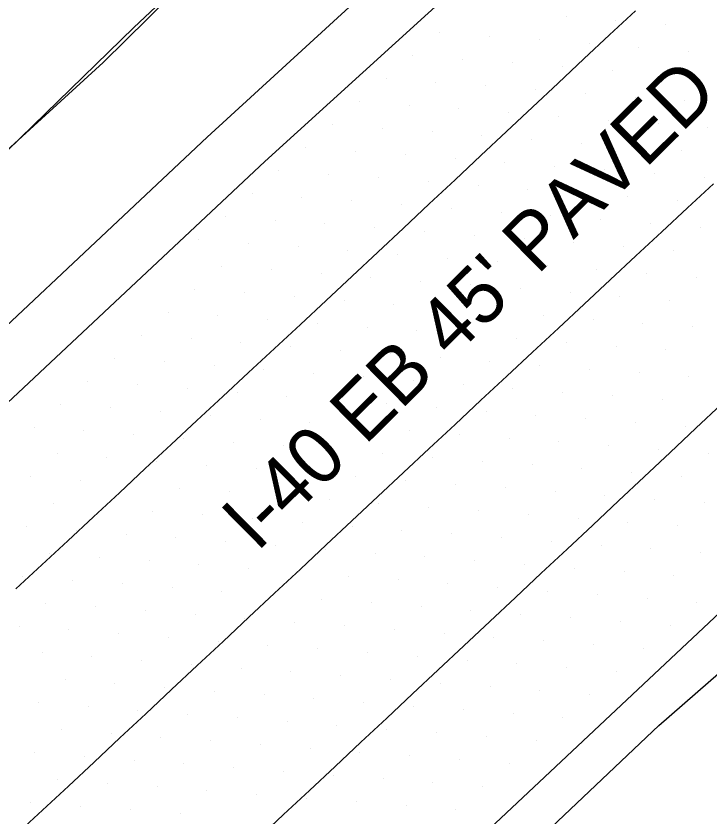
# Model space of a CAD drawing. Extents: x 1548934 to 1561348, y 809680 to 824075.
# Drawn here: x 1552081 to 1552130.1, y 810906.3 to 810963 of the extents above; entities that cross this region are included whole.
import ezdxf

# ---------------------------------------------------------------- set-up
doc = ezdxf.new("R2010")
doc.units = 0
for name, color, linetype in [('E_NCDOT_Vertical_Profile_Ground_Line', 7, 'Continuous'), ('Exist DTM Scan Elevation Point', 7, 'Continuous'), ('Exist Guardrail Cable Guide Rail', 7, 'Continuous'), ('Exist Roads EOP Text', 7, 'Continuous'), ('P_RDY_Terminator_Cell', 7, 'Continuous'), ('PH Exist DTM Breakline', 7, 'Continuous')]:
    doc.layers.add(name, color=color, linetype=linetype)

msp = doc.modelspace()

# ---------------------------------------------------------------- linework, layer by layer
at = {"layer": 'E_NCDOT_Vertical_Profile_Ground_Line'}
for points in [[(1551914.733, 810783.326), (1551936.975, 810803.465), (1551959.182, 810823.64), (1551981.364, 810843.843), (1552003.226, 810864.385), (1552025.148, 810884.865), (1552043.694, 810901.636), (1552062.107, 810918.548), (1552080.398, 810935.59), (1552098.623, 810952.701), (1552117.113, 810969.532), (1552135.352, 810986.629), (1552153.57, 811003.748), (1552171.877, 811020.773), (1552190.026, 811037.966), (1552208.08, 811055.241), (1552226.135, 811072.468)], [(1551911.033, 810719.298), (1551923.424, 810730.276), (1551945.867, 810750.201), (1551968.023, 810770.431), (1551990.144, 810790.698), (1552012.283, 810810.947), (1552034.431, 810831.185), (1552056.423, 810851.59), (1552074.962, 810868.368), (1552093.191, 810885.476), (1552111.451, 810902.55), (1552129.675, 810919.663), (1552147.898, 810936.778), (1552166.164, 810953.847), (1552184.38, 810970.968), (1552202.566, 810988.121), (1552220.715, 811005.314), (1552238.802, 811022.599), (1552256.952, 811039.884)]]:
    msp.add_lwpolyline(points, dxfattribs=at)
at = {"layer": 'Exist DTM Scan Elevation Point'}
for p, q in [((1552119.942, 810962.937), (1552119.942, 810962.937)), ((1552123.467, 810962.669), (1552123.467, 810962.669)), ((1552126.992, 810962.401), (1552126.992, 810962.401)), ((1552110.995, 810961.843), (1552110.995, 810961.843)), ((1552114.521, 810961.576), (1552114.521, 810961.576)), ((1552118.046, 810961.308), (1552118.046, 810961.308)), ((1552121.571, 810961.04), (1552121.571, 810961.04)), ((1552125.096, 810960.773), (1552125.096, 810960.773)), ((1552128.621, 810960.505), (1552128.621, 810960.505)), ((1552109.099, 810960.214), (1552109.099, 810960.214)), ((1552112.624, 810959.947), (1552112.624, 810959.947)), ((1552116.149, 810959.679), (1552116.149, 810959.679)), ((1552119.675, 810959.411), (1552119.675, 810959.411)), ((1552123.2, 810959.144), (1552123.2, 810959.144)), ((1552126.725, 810958.876), (1552126.725, 810958.876)), ((1552107.203, 810958.585), (1552107.203, 810958.585)), ((1552110.728, 810958.318), (1552110.728, 810958.318)), ((1552114.253, 810958.05), (1552114.253, 810958.05)), ((1552117.778, 810957.782), (1552117.778, 810957.782)), ((1552121.303, 810957.515), (1552121.303, 810957.515)), ((1552105.306, 810956.956), (1552105.306, 810956.956)), ((1552124.828, 810957.247), (1552124.828, 810957.247)), ((1552128.354, 810956.979), (1552128.354, 810956.979)), ((1552108.831, 810956.689), (1552108.831, 810956.689)), ((1552112.356, 810956.421), (1552112.356, 810956.421)), ((1552115.882, 810956.154), (1552115.882, 810956.154)), ((1552119.407, 810955.886), (1552119.407, 810955.886)), ((1552103.41, 810955.327), (1552103.41, 810955.327)), ((1552122.932, 810955.618), (1552122.932, 810955.618)), ((1552126.457, 810955.351), (1552126.457, 810955.351)), ((1552106.935, 810955.06), (1552106.935, 810955.06)), ((1552110.46, 810954.792), (1552110.46, 810954.792)), ((1552129.983, 810955.083), (1552129.983, 810955.083)), ((1552113.985, 810954.525), (1552113.985, 810954.525)), ((1552117.511, 810954.257), (1552117.511, 810954.257)), ((1552101.513, 810953.698), (1552101.513, 810953.698)), ((1552121.036, 810953.989), (1552121.036, 810953.989)), ((1552124.561, 810953.722), (1552124.561, 810953.722)), ((1552105.038, 810953.431), (1552105.038, 810953.431)), ((1552108.564, 810953.163), (1552108.564, 810953.163)), ((1552128.086, 810953.454), (1552128.086, 810953.454)), ((1552112.089, 810952.896), (1552112.089, 810952.896)), ((1552115.614, 810952.628), (1552115.614, 810952.628)), ((1552099.617, 810952.07), (1552099.617, 810952.07)), ((1552119.139, 810952.36), (1552119.139, 810952.36)), ((1552122.665, 810952.093), (1552122.665, 810952.093)), ((1552103.142, 810951.802), (1552103.142, 810951.802)), ((1552106.667, 810951.534), (1552106.667, 810951.534)), ((1552126.19, 810951.825), (1552126.19, 810951.825)), ((1552129.715, 810951.558), (1552129.715, 810951.558)), ((1552110.193, 810951.267), (1552110.193, 810951.267)), ((1552113.718, 810950.999), (1552113.718, 810950.999)), ((1552117.243, 810950.731), (1552117.243, 810950.731)), ((1552097.721, 810950.441), (1552097.721, 810950.441)), ((1552101.246, 810950.173), (1552101.246, 810950.173)), ((1552120.768, 810950.464), (1552120.768, 810950.464)), ((1552124.294, 810950.196), (1552124.294, 810950.196)), ((1552104.771, 810949.905), (1552104.771, 810949.905)), ((1552108.296, 810949.638), (1552108.296, 810949.638)), ((1552127.819, 810949.929), (1552127.819, 810949.929)), ((1552111.821, 810949.37), (1552111.821, 810949.37)), ((1552115.347, 810949.102), (1552115.347, 810949.102)), ((1552095.824, 810948.811), (1552095.824, 810948.811)), ((1552099.349, 810948.544), (1552099.349, 810948.544)), ((1552118.872, 810948.835), (1552118.872, 810948.835)), ((1552122.397, 810948.567), (1552122.397, 810948.567)), ((1552102.875, 810948.276), (1552102.875, 810948.276)), ((1552106.4, 810948.009), (1552106.4, 810948.009)), ((1552125.922, 810948.3), (1552125.922, 810948.3)), ((1552129.448, 810948.032), (1552129.448, 810948.032)), ((1552109.925, 810947.741), (1552109.925, 810947.741)), ((1552113.45, 810947.473), (1552113.45, 810947.473)), ((1552093.927, 810947.182), (1552093.927, 810947.182)), ((1552097.453, 810946.915), (1552097.453, 810946.915)), ((1552116.975, 810947.206), (1552116.975, 810947.206)), ((1552120.501, 810946.938), (1552120.501, 810946.938)), ((1552100.978, 810946.647), (1552100.978, 810946.647)), ((1552104.504, 810946.38), (1552104.504, 810946.38)), ((1552124.026, 810946.671), (1552124.026, 810946.671)), ((1552127.551, 810946.403), (1552127.551, 810946.403)), ((1552108.028, 810946.112), (1552108.028, 810946.112)), ((1552111.554, 810945.844), (1552111.554, 810945.844)), ((1552095.556, 810945.286), (1552095.556, 810945.286)), ((1552115.079, 810945.577), (1552115.079, 810945.577)), ((1552118.604, 810945.309), (1552118.604, 810945.309)), ((1552122.13, 810945.042), (1552122.13, 810945.042)), ((1552099.082, 810945.018), (1552099.082, 810945.018)), ((1552102.607, 810944.751), (1552102.607, 810944.751)), ((1552106.132, 810944.483), (1552106.132, 810944.483)), ((1552125.655, 810944.774), (1552125.655, 810944.774)), ((1552129.18, 810944.507), (1552129.18, 810944.507)), ((1552109.657, 810944.216), (1552109.657, 810944.216)), ((1552113.183, 810943.948), (1552113.183, 810943.948)), ((1552093.66, 810943.657), (1552093.66, 810943.657)), ((1552097.185, 810943.389), (1552097.185, 810943.389)), ((1552116.708, 810943.681), (1552116.708, 810943.681)), ((1552120.233, 810943.413), (1552120.233, 810943.413)), ((1552100.711, 810943.122), (1552100.711, 810943.122)), ((1552104.236, 810942.854), (1552104.236, 810942.854)), ((1552123.759, 810943.145), (1552123.759, 810943.145)), ((1552127.284, 810942.878), (1552127.284, 810942.878)), ((1552107.761, 810942.587), (1552107.761, 810942.587)), ((1552111.286, 810942.319), (1552111.286, 810942.319)), ((1552091.764, 810942.028), (1552091.764, 810942.028)), ((1552095.289, 810941.761), (1552095.289, 810941.761)), ((1552114.812, 810942.052), (1552114.812, 810942.052)), ((1552118.337, 810941.784), (1552118.337, 810941.784)), ((1552098.814, 810941.493), (1552098.814, 810941.493)), ((1552102.339, 810941.225), (1552102.339, 810941.225)), ((1552121.862, 810941.516), (1552121.862, 810941.516)), ((1552125.387, 810941.249), (1552125.387, 810941.249)), ((1552105.865, 810940.958), (1552105.865, 810940.958)), ((1552109.39, 810940.69), (1552109.39, 810940.69)), ((1552128.913, 810940.981), (1552128.913, 810940.981)), ((1552089.867, 810940.399), (1552089.867, 810940.399)), ((1552093.392, 810940.132), (1552093.392, 810940.132)), ((1552112.915, 810940.423), (1552112.915, 810940.423)), ((1552116.44, 810940.155), (1552116.44, 810940.155)), ((1552096.918, 810939.864), (1552096.918, 810939.864)), ((1552100.443, 810939.596), (1552100.443, 810939.596)), ((1552119.966, 810939.888), (1552119.966, 810939.888)), ((1552123.491, 810939.62), (1552123.491, 810939.62)), ((1552103.968, 810939.329), (1552103.968, 810939.329)), ((1552107.493, 810939.061), (1552107.493, 810939.061)), ((1552127.016, 810939.352), (1552127.016, 810939.352)), ((1552087.971, 810938.77), (1552087.971, 810938.77)), ((1552091.496, 810938.503), (1552091.496, 810938.503)), ((1552111.019, 810938.794), (1552111.019, 810938.794)), ((1552114.544, 810938.526), (1552114.544, 810938.526)), ((1552118.069, 810938.259), (1552118.069, 810938.259)), ((1552095.021, 810938.235), (1552095.021, 810938.235)), ((1552098.547, 810937.967), (1552098.547, 810937.967)), ((1552102.072, 810937.7), (1552102.072, 810937.7)), ((1552121.595, 810937.991), (1552121.595, 810937.991)), ((1552125.12, 810937.723), (1552125.12, 810937.723)), ((1552086.075, 810937.141), (1552086.075, 810937.141)), ((1552105.597, 810937.432), (1552105.597, 810937.432)), ((1552109.122, 810937.165), (1552109.122, 810937.165)), ((1552128.645, 810937.456), (1552128.645, 810937.456)), ((1552089.6, 810936.874), (1552089.6, 810936.874)), ((1552093.125, 810936.606), (1552093.125, 810936.606)), ((1552112.648, 810936.897), (1552112.648, 810936.897)), ((1552116.173, 810936.63), (1552116.173, 810936.63)), ((1552096.65, 810936.339), (1552096.65, 810936.339)), ((1552100.175, 810936.071), (1552100.175, 810936.071)), ((1552119.698, 810936.362), (1552119.698, 810936.362)), ((1552123.224, 810936.095), (1552123.224, 810936.095)), ((1552084.178, 810935.513), (1552084.178, 810935.513)), ((1552103.701, 810935.803), (1552103.701, 810935.803)), ((1552107.226, 810935.536), (1552107.226, 810935.536)), ((1552126.749, 810935.827), (1552126.749, 810935.827)), ((1552087.704, 810935.245), (1552087.704, 810935.245)), ((1552091.229, 810934.977), (1552091.229, 810934.977)), ((1552110.751, 810935.268), (1552110.751, 810935.268)), ((1552114.277, 810935.001), (1552114.277, 810935.001)), ((1552094.754, 810934.71), (1552094.754, 810934.71)), ((1552098.279, 810934.442), (1552098.279, 810934.442)), ((1552117.802, 810934.733), (1552117.802, 810934.733)), ((1552121.327, 810934.466), (1552121.327, 810934.466)), ((1552082.282, 810933.884), (1552082.282, 810933.884)), ((1552101.804, 810934.174), (1552101.804, 810934.174)), ((1552105.33, 810933.907), (1552105.33, 810933.907)), ((1552124.853, 810934.198), (1552124.853, 810934.198)), ((1552128.378, 810933.931), (1552128.378, 810933.931)), ((1552085.807, 810933.616), (1552085.807, 810933.616)), ((1552089.332, 810933.348), (1552089.332, 810933.348)), ((1552108.855, 810933.639), (1552108.855, 810933.639)), ((1552112.38, 810933.372), (1552112.38, 810933.372)), ((1552092.858, 810933.081), (1552092.858, 810933.081)), ((1552096.383, 810932.813), (1552096.383, 810932.813)), ((1552115.906, 810933.104), (1552115.906, 810933.104)), ((1552119.431, 810932.837), (1552119.431, 810932.837)), ((1552099.908, 810932.545), (1552099.908, 810932.545)), ((1552103.433, 810932.278), (1552103.433, 810932.278)), ((1552106.959, 810932.01), (1552106.959, 810932.01)), ((1552122.956, 810932.569), (1552122.956, 810932.569)), ((1552126.481, 810932.302), (1552126.481, 810932.302)), ((1552130.007, 810932.034), (1552130.007, 810932.034)), ((1552083.911, 810931.987), (1552083.911, 810931.987)), ((1552087.436, 810931.719), (1552087.436, 810931.719)), ((1552090.961, 810931.452), (1552090.961, 810931.452)), ((1552110.484, 810931.743), (1552110.484, 810931.743)), ((1552114.009, 810931.475), (1552114.009, 810931.475)), ((1552094.486, 810931.184), (1552094.486, 810931.184)), ((1552098.012, 810930.917), (1552098.012, 810930.917)), ((1552117.534, 810931.208), (1552117.534, 810931.208)), ((1552121.06, 810930.94), (1552121.06, 810930.94)), ((1552082.014, 810930.358), (1552082.014, 810930.358)), ((1552101.537, 810930.649), (1552101.537, 810930.649)), ((1552105.062, 810930.381), (1552105.062, 810930.381)), ((1552124.585, 810930.673), (1552124.585, 810930.673)), ((1552128.111, 810930.405), (1552128.111, 810930.405)), ((1552085.54, 810930.09), (1552085.54, 810930.09)), ((1552089.065, 810929.823), (1552089.065, 810929.823)), ((1552108.587, 810930.114), (1552108.587, 810930.114)), ((1552112.113, 810929.846), (1552112.113, 810929.846)), ((1552092.59, 810929.555), (1552092.59, 810929.555)), ((1552096.115, 810929.288), (1552096.115, 810929.288)), ((1552115.638, 810929.579), (1552115.638, 810929.579)), ((1552119.163, 810929.311), (1552119.163, 810929.311)), ((1552099.64, 810929.02), (1552099.64, 810929.02)), ((1552103.166, 810928.753), (1552103.166, 810928.753)), ((1552122.689, 810929.044), (1552122.689, 810929.044)), ((1552126.214, 810928.777), (1552126.214, 810928.777)), ((1552083.643, 810928.462), (1552083.643, 810928.462)), ((1552087.168, 810928.194), (1552087.168, 810928.194)), ((1552106.691, 810928.485), (1552106.691, 810928.485)), ((1552110.216, 810928.217), (1552110.216, 810928.217)), ((1552129.74, 810928.509), (1552129.74, 810928.509)), ((1552090.694, 810927.926), (1552090.694, 810927.926)), ((1552094.219, 810927.659), (1552094.219, 810927.659)), ((1552113.742, 810927.95), (1552113.742, 810927.95)), ((1552117.267, 810927.682), (1552117.267, 810927.682)), ((1552097.744, 810927.391), (1552097.744, 810927.391)), ((1552101.269, 810927.124), (1552101.269, 810927.124)), ((1552120.792, 810927.415), (1552120.792, 810927.415)), ((1552124.318, 810927.148), (1552124.318, 810927.148)), ((1552081.747, 810926.833), (1552081.747, 810926.833)), ((1552085.272, 810926.565), (1552085.272, 810926.565)), ((1552104.795, 810926.856), (1552104.795, 810926.856)), ((1552108.32, 810926.589), (1552108.32, 810926.589)), ((1552127.844, 810926.88), (1552127.844, 810926.88)), ((1552088.797, 810926.297), (1552088.797, 810926.297)), ((1552092.322, 810926.03), (1552092.322, 810926.03)), ((1552111.845, 810926.321), (1552111.845, 810926.321)), ((1552115.371, 810926.053), (1552115.371, 810926.053)), ((1552118.896, 810925.786), (1552118.896, 810925.786)), ((1552095.848, 810925.762), (1552095.848, 810925.762)), ((1552099.373, 810925.495), (1552099.373, 810925.495)), ((1552102.898, 810925.227), (1552102.898, 810925.227)), ((1552122.422, 810925.519), (1552122.422, 810925.519)), ((1552125.947, 810925.251), (1552125.947, 810925.251)), ((1552083.376, 810924.936), (1552083.376, 810924.936)), ((1552086.901, 810924.668), (1552086.901, 810924.668)), ((1552106.424, 810924.96), (1552106.424, 810924.96)), ((1552109.949, 810924.692), (1552109.949, 810924.692)), ((1552129.473, 810924.984), (1552129.473, 810924.984)), ((1552090.426, 810924.401), (1552090.426, 810924.401)), ((1552093.951, 810924.133), (1552093.951, 810924.133)), ((1552113.474, 810924.424), (1552113.474, 810924.424)), ((1552117, 810924.157), (1552117, 810924.157)), ((1552097.477, 810923.866), (1552097.477, 810923.866)), ((1552101.002, 810923.598), (1552101.002, 810923.598)), ((1552120.525, 810923.89), (1552120.525, 810923.89)), ((1552124.051, 810923.623), (1552124.051, 810923.623)), ((1552081.479, 810923.307), (1552081.479, 810923.307)), ((1552085.005, 810923.04), (1552085.005, 810923.04)), ((1552104.527, 810923.331), (1552104.527, 810923.331)), ((1552108.053, 810923.063), (1552108.053, 810923.063)), ((1552127.577, 810923.355), (1552127.577, 810923.355)), ((1552088.53, 810922.772), (1552088.53, 810922.772)), ((1552092.055, 810922.504), (1552092.055, 810922.504)), ((1552111.578, 810922.796), (1552111.578, 810922.796)), ((1552115.103, 810922.528), (1552115.103, 810922.528)), ((1552095.58, 810922.237), (1552095.58, 810922.237)), ((1552099.106, 810921.969), (1552099.106, 810921.969)), ((1552118.629, 810922.261), (1552118.629, 810922.261)), ((1552122.155, 810921.994), (1552122.155, 810921.994)), ((1552083.108, 810921.411), (1552083.108, 810921.411)), ((1552102.631, 810921.702), (1552102.631, 810921.702)), ((1552106.156, 810921.434), (1552106.156, 810921.434)), ((1552125.681, 810921.727), (1552125.681, 810921.727)), ((1552129.206, 810921.459), (1552129.206, 810921.459)), ((1552086.633, 810921.143), (1552086.633, 810921.143)), ((1552090.159, 810920.875), (1552090.159, 810920.875)), ((1552109.681, 810921.167), (1552109.681, 810921.167)), ((1552113.207, 810920.899), (1552113.207, 810920.899)), ((1552093.684, 810920.608), (1552093.684, 810920.608)), ((1552097.209, 810920.34), (1552097.209, 810920.34)), ((1552116.732, 810920.632), (1552116.732, 810920.632)), ((1552120.258, 810920.365), (1552120.258, 810920.365)), ((1552081.212, 810919.782), (1552081.212, 810919.782)), ((1552100.735, 810920.073), (1552100.735, 810920.073)), ((1552104.26, 810919.805), (1552104.26, 810919.805)), ((1552107.785, 810919.538), (1552107.785, 810919.538)), ((1552123.784, 810920.098), (1552123.784, 810920.098)), ((1552127.31, 810919.831), (1552127.31, 810919.831)), ((1552084.737, 810919.514), (1552084.737, 810919.514)), ((1552088.262, 810919.246), (1552088.262, 810919.246)), ((1552091.787, 810918.979), (1552091.787, 810918.979)), ((1552111.31, 810919.27), (1552111.31, 810919.27)), ((1552114.836, 810919.003), (1552114.836, 810919.003)), ((1552095.313, 810918.711), (1552095.313, 810918.711)), ((1552098.838, 810918.444), (1552098.838, 810918.444)), ((1552118.362, 810918.736), (1552118.362, 810918.736)), ((1552121.888, 810918.469), (1552121.888, 810918.469)), ((1552082.84, 810917.885), (1552082.84, 810917.885)), ((1552102.363, 810918.176), (1552102.363, 810918.176)), ((1552105.889, 810917.909), (1552105.889, 810917.909)), ((1552125.414, 810918.202), (1552125.414, 810918.202)), ((1552086.366, 810917.618), (1552086.366, 810917.618)), ((1552089.891, 810917.35), (1552089.891, 810917.35)), ((1552109.414, 810917.641), (1552109.414, 810917.641)), ((1552112.94, 810917.374), (1552112.94, 810917.374)), ((1552093.416, 810917.082), (1552093.416, 810917.082)), ((1552096.942, 810916.815), (1552096.942, 810916.815)), ((1552116.465, 810917.107), (1552116.465, 810917.107)), ((1552119.991, 810916.84), (1552119.991, 810916.84)), ((1552100.467, 810916.547), (1552100.467, 810916.547)), ((1552103.992, 810916.28), (1552103.992, 810916.28)), ((1552123.517, 810916.573), (1552123.517, 810916.573)), ((1552084.469, 810915.989), (1552084.469, 810915.989)), ((1552087.995, 810915.721), (1552087.995, 810915.721)), ((1552107.518, 810916.012), (1552107.518, 810916.012)), ((1552111.043, 810915.745), (1552111.043, 810915.745)), ((1552091.52, 810915.454), (1552091.52, 810915.454)), ((1552095.045, 810915.186), (1552095.045, 810915.186)), ((1552114.569, 810915.478), (1552114.569, 810915.478)), ((1552118.095, 810915.211), (1552118.095, 810915.211)), ((1552098.571, 810914.918), (1552098.571, 810914.918)), ((1552102.096, 810914.651), (1552102.096, 810914.651)), ((1552121.621, 810914.944), (1552121.621, 810914.944)), ((1552082.573, 810914.36), (1552082.573, 810914.36)), ((1552086.098, 810914.092), (1552086.098, 810914.092)), ((1552105.621, 810914.383), (1552105.621, 810914.383)), ((1552109.147, 810914.116), (1552109.147, 810914.116)), ((1552089.624, 810913.825), (1552089.624, 810913.825)), ((1552093.149, 810913.557), (1552093.149, 810913.557)), ((1552112.672, 810913.849), (1552112.672, 810913.849)), ((1552116.198, 810913.582), (1552116.198, 810913.582)), ((1552119.724, 810913.315), (1552119.724, 810913.315)), ((1552096.674, 810913.29), (1552096.674, 810913.29)), ((1552100.2, 810913.022), (1552100.2, 810913.022)), ((1552103.725, 810912.754), (1552103.725, 810912.754)), ((1552084.202, 810912.463), (1552084.202, 810912.463)), ((1552087.727, 810912.196), (1552087.727, 810912.196)), ((1552107.25, 810912.487), (1552107.25, 810912.487)), ((1552110.776, 810912.22), (1552110.776, 810912.22)), ((1552091.253, 810911.928), (1552091.253, 810911.928)), ((1552094.778, 810911.661), (1552094.778, 810911.661)), ((1552114.302, 810911.953), (1552114.302, 810911.953)), ((1552117.828, 810911.686), (1552117.828, 810911.686)), ((1552098.303, 810911.393), (1552098.303, 810911.393)), ((1552101.829, 810911.126), (1552101.829, 810911.126)), ((1552082.306, 810910.834), (1552082.306, 810910.834)), ((1552085.831, 810910.567), (1552085.831, 810910.567)), ((1552105.354, 810910.858), (1552105.354, 810910.858)), ((1552108.88, 810910.591), (1552108.88, 810910.591)), ((1552089.356, 810910.299), (1552089.356, 810910.299)), ((1552092.881, 810910.032), (1552092.881, 810910.032)), ((1552112.406, 810910.324), (1552112.406, 810910.324)), ((1552115.931, 810910.057), (1552115.931, 810910.057)), ((1552096.407, 810909.764), (1552096.407, 810909.764)), ((1552099.932, 810909.497), (1552099.932, 810909.497)), ((1552083.934, 810908.938), (1552083.934, 810908.938)), ((1552103.458, 810909.229), (1552103.458, 810909.229)), ((1552106.983, 810908.962), (1552106.983, 810908.962)), ((1552087.46, 810908.67), (1552087.46, 810908.67)), ((1552090.985, 810908.403), (1552090.985, 810908.403)), ((1552110.509, 810908.695), (1552110.509, 810908.695)), ((1552114.035, 810908.428), (1552114.035, 810908.428)), ((1552094.51, 810908.135), (1552094.51, 810908.135)), ((1552098.036, 810907.868), (1552098.036, 810907.868)), ((1552082.038, 810907.309), (1552082.038, 810907.309)), ((1552101.561, 810907.6), (1552101.561, 810907.6)), ((1552105.087, 810907.333), (1552105.087, 810907.333)), ((1552085.563, 810907.041), (1552085.563, 810907.041)), ((1552089.089, 810906.774), (1552089.089, 810906.774)), ((1552092.614, 810906.506), (1552092.614, 810906.506)), ((1552108.613, 810907.066), (1552108.613, 810907.066)), ((1552112.139, 810906.799), (1552112.139, 810906.799))]:
    msp.add_line(p, q, dxfattribs=at)
at = {"layer": 'Exist Guardrail Cable Guide Rail'}
msp.add_lwpolyline([(1552034.503, 810911.002), (1552045.539, 810921.16), (1552056.557, 810931.339), (1552067.59, 810941.5), (1552078.575, 810951.713), (1552089.33, 810962.174), (1552100.256, 810972.449), (1552111.51, 810982.374), (1552122.531, 810992.55), (1552133.503, 811002.777), (1552144.462, 811013.018), (1552155.347, 811023.34), (1552166.3, 811033.588), (1552177.229, 811043.861), (1552188.033, 811054.269), (1552198.862, 811064.649), (1552209.702, 811075.02)], dxfattribs=at)
at = {"layer": 'P_RDY_Terminator_Cell'}
for points in [[(1552080.997, 810922.424), (1552082.827, 810924.127), (1552084.658, 810925.829), (1552086.488, 810927.532), (1552088.318, 810929.235), (1552090.149, 810930.938), (1552091.979, 810932.641), (1552093.81, 810934.343), (1552095.64, 810936.046), (1552097.471, 810937.749), (1552099.301, 810939.452), (1552101.131, 810941.154), (1552102.962, 810942.857), (1552104.792, 810944.561), (1552106.615, 810946.271), (1552108.439, 810947.981), (1552110.263, 810949.691), (1552112.086, 810951.401), (1552113.91, 810953.111), (1552115.734, 810954.821), (1552117.557, 810956.531), (1552119.381, 810958.241), (1552121.205, 810959.951), (1552123.028, 810961.661), (1552124.852, 810963.371)], [(1552081.044, 810905.049), (1552082.876, 810906.75), (1552084.707, 810908.452), (1552086.533, 810910.16), (1552088.358, 810911.868), (1552090.183, 810913.577), (1552092.008, 810915.285), (1552093.833, 810916.994), (1552095.658, 810918.703), (1552097.483, 810920.411), (1552099.308, 810922.12), (1552101.133, 810923.828), (1552102.958, 810925.537), (1552104.783, 810927.245), (1552106.608, 810928.954), (1552108.434, 810930.662), (1552110.263, 810932.367), (1552112.091, 810934.072), (1552113.919, 810935.777), (1552115.748, 810937.482), (1552117.576, 810939.187), (1552119.405, 810940.892), (1552121.233, 810942.596), (1552123.062, 810944.301), (1552124.89, 810946.006), (1552126.718, 810947.711), (1552128.547, 810949.416), (1552130.375, 810951.121)], [(1552130.944, 810935.509), (1552129.124, 810933.795), (1552127.304, 810932.08), (1552125.484, 810930.366), (1552123.664, 810928.652), (1552121.84, 810926.943), (1552120.015, 810925.234), (1552118.191, 810923.525), (1552116.366, 810921.815), (1552114.542, 810920.106), (1552112.718, 810918.397), (1552110.893, 810916.688), (1552109.069, 810914.978), (1552107.244, 810913.269), (1552105.42, 810911.56), (1552103.595, 810909.851), (1552101.771, 810908.141), (1552099.947, 810906.432), (1552098.122, 810904.723)]]:
    msp.add_lwpolyline(points, dxfattribs=at)
at = {"layer": 'PH Exist DTM Breakline'}
for points in [[(1552218.727, 811089.351), (1552201.076, 811070.073), (1552178.519, 811047.989), (1552164.673, 811033.048), (1552143.451, 811012.548), (1552122.543, 810992.993), (1552103.054, 810975.369), (1552087.173, 810959.702), (1552063.934, 810938.512), (1552042.132, 810918.102), (1552024.774, 810903.375), (1552009.199, 810888.66)], [(1552012.08, 810883.998), (1552029.792, 810897.863), (1552053.549, 810917.035), (1552071.968, 810933.223), (1552094.541, 810954.417), (1552113.521, 810971.838), (1552133.45, 810990.71), (1552150.941, 811006.148), (1552168.695, 811023.351), (1552192.93, 811048.727), (1552219.348, 811074.647), (1552224.762, 811079.939)], [(1552034.682, 810827.336), (1552045.39, 810836.839), (1552057.445, 810848.653), (1552073.238, 810863.394), (1552087.49, 810876.306), (1552110.392, 810897.468), (1552126.518, 810912.756), (1552142.148, 810926.371), (1552156.577, 810940.789), (1552169.312, 810953.067), (1552184.045, 810967.444), (1552198.882, 810980.586), (1552216.514, 810997.979), (1552233.022, 811012.993), (1552255.095, 811034.131)]]:
    msp.add_lwpolyline(points, dxfattribs=at)

# ---------------------------------------------------------------- texts
at = {"layer": 'Exist Roads EOP Text'}
msp.add_text("I-40 EB 45' PAVED", height=4.02, rotation=44.6621, dxfattribs=at).set_placement((1552098.049, 810924.978))

doc.saveas('drawing.dxf')
